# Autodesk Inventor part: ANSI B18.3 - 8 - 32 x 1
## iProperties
IsCustomPart: 0
Created: 2008-02
Part Number: ANSI B18.3 - 8 - 32 x 1
Material: Steel, Mild
Description: Hexagon Socket Button Head Cap Screw
Document SubType Name: Modeling
Standard: ANSI B18.3
Standard Revision: 2003
Standards Organization: ANSI
Language: en-US
Size Designation: 8 - 32 x 1
Categories: <MemberInstance><Categories><Category DisplayName="Fasteners" InternalName="e4da775c-781d-43d5-af7c-5136215cf5a6" Mnemonic="FSTN"><Category DisplayName="Bolts"
Density: 1 g/cm^3
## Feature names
1. Body [Revolution]
2. Slot [Extrusion]
3. Fillet1
4. Chamfer1
5. Fillet2
